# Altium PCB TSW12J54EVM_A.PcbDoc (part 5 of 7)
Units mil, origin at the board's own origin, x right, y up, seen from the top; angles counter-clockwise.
Board outline 6301 x 2680 mil, 10 copper layers (Top Layer - L1, Gnd-Plane - L2, Signals - L3, Gnd-Plane - L4, Pwr Plane - L5, Signals - L6, Gnd-Plane - L7, Signals - L8, Gnd-Plane - L9, Bottom Layer - L10), stack 57.8 mil thick; 650 components, 374 nets, 2074 pads, 1402 vias.
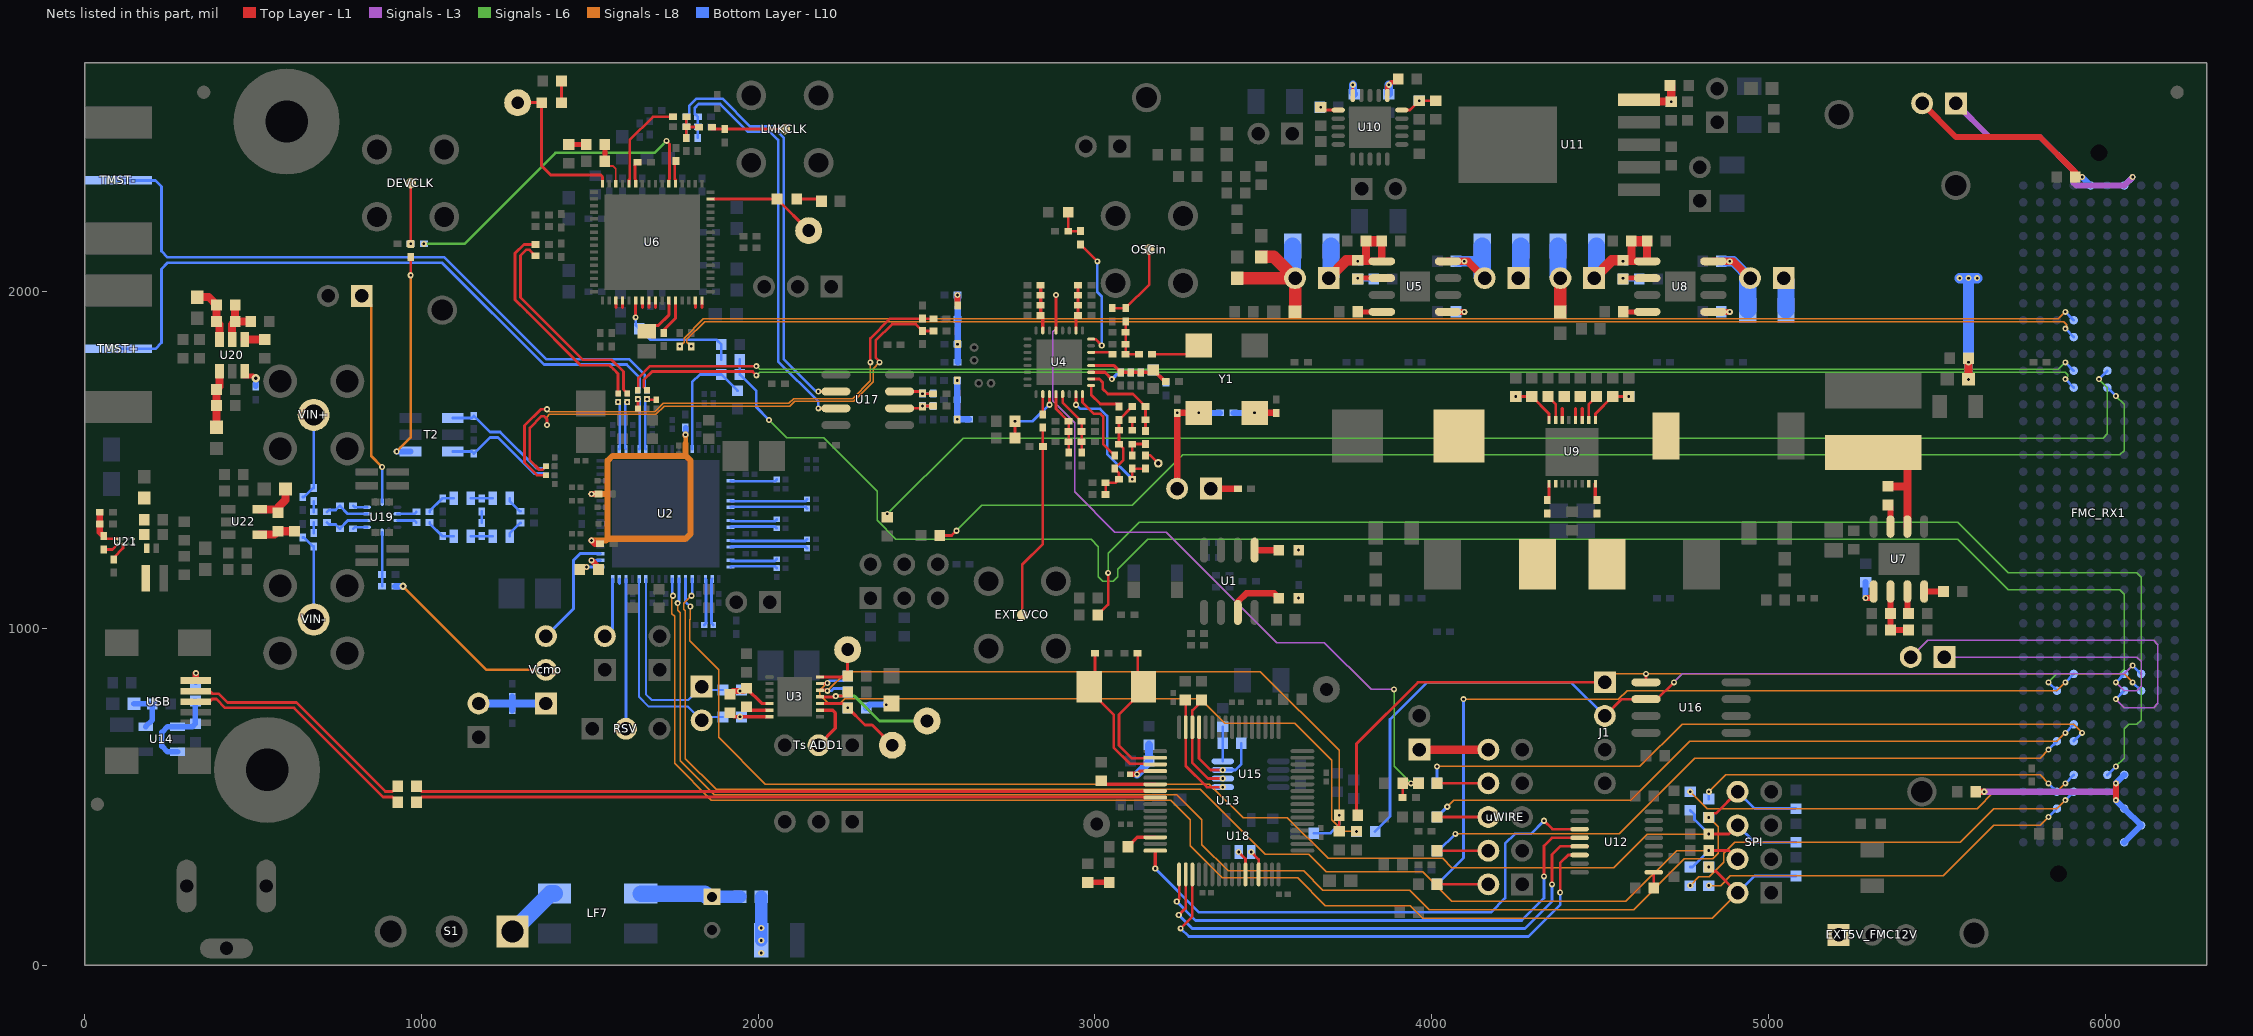
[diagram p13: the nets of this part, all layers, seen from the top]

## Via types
v1: diameter 18, hole 8, Top Layer - L1 to Bottom Layer - L10, tented both sides, 1120 vias
v2: diameter 19.68, hole 7.87, Top Layer - L1 to Bottom Layer - L10, 99 vias
v3: diameter 18, hole 8, Top Layer - L1 to Bottom Layer - L10, tented bottom, 42 vias
v4: diameter 18, hole 8, Top Layer - L1 to Bottom Layer - L10, tented top, 36 vias
v5: diameter 25, hole 10, Top Layer - L1 to Bottom Layer - L10, tented both sides, 32 vias
v6: diameter 21.46, hole 10, Top Layer - L1 to Bottom Layer - L10, tented both sides, 26 vias
v7: diameter 18, hole 8.01, Top Layer - L1 to Bottom Layer - L10, tented both sides, 16 vias
v8: diameter 18, hole 8.01, Top Layer - L1 to Bottom Layer - L10, tented bottom, 16 vias
v9: diameter 25.98, hole 12.99, Top Layer - L1 to Bottom Layer - L10, tented top, 8 vias
v10: diameter 19.68, hole 7.87, Top Layer - L1 to Bottom Layer - L10, tented top, 5 vias
v11: diameter 126, hole 106, Top Layer - L1 to Bottom Layer - L10, tented top, 2 vias

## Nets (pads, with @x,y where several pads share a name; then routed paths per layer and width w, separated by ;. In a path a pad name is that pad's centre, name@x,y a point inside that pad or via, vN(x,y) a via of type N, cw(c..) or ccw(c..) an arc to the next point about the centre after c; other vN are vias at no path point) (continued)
NetC14_2: C14.2 U2.38 | length 139.9
  Bottom Layer - L10 w8: U2.38@1918.3,1438.43 1920.14,1436.58 2049.7,1436.58 C14.2@2055.2,1442.08
NetC15_2: C15.2 U2.42 | length 229.9
  Bottom Layer - L10 w8: U2.42@1918.3,1359.68 1920.14,1361.53 2139.7,1361.53 C15.2@2145.2,1356.03
NetC16_2: C16.2 C18.2 C19.2 U2.5 U2.12 U2.29 | length 1287.4
  Top Layer - L1 w18: v1(1505.26,1261.26) 1515.31,1251.21 C18.2@1530.57,1251.2 ; v1(1505.26,1399.05) C19.2@1525.52,1399.05
  Signals - L8 w13: 1784.44,1549.33 v1@1784.44,1570.92
  Signals - L8 w18: v1(1505.26,1261.26) 1548.22,1261.26 1553.14,1266.18 ; v1(1505.26,1399.05) 1553.14,1399.05 ; 1552.79,1497.48 1567.56,1512.24 1784.79,1512.24 ; 1553.14,1497.83 1553.14,1266.18 ; 1784.44,1549.33 1784.44,1512.59 1799.2,1497.83 1799.2,1280.6 1784.79,1266.18 1553.14,1266.18 ; v1@1784.44,1570.92 v1(1784.44,1575.13)
  Bottom Layer - L10 w9: v1(1505.26,1261.26) U2.5@1532.47,1261.26 ; v1(1505.26,1399.05) U2.12@1532.47,1399.06 ; U2.29@1784.44,1532.91 v1(1784.44,1575.13)
  Bottom Layer - L10 w16: v1(1784.44,1575.13) C16.2@1784.44,1595.94
NetC17_2: C17.2 U2.41 | length 229.9
  Bottom Layer - L10 w8: U2.41@1918.3,1379.37 1920.14,1377.53 2139.7,1377.53 C17.2@2145.2,1383.03
NetC20_2: C20.2 U2.45 | length 139.9
  Bottom Layer - L10 w8: U2.45@1918.3,1300.63 1920.14,1302.47 2049.7,1302.47 C20.2@2055.2,1296.97
NetC21_2: C21.2 U2.44 | length 139.9
  Bottom Layer - L10 w8: U2.44@1918.3,1320.31 1920.14,1318.47 2049.7,1318.47 C21.2@2055.2,1323.97
NetC22_2: C22.2 R7.2 U2.48 | length 229.9
  Bottom Layer - L10 w8: U2.48@1918.3,1241.57 1920.14,1243.42 2139.7,1243.42 R7.2@2145.2,1237.92
NetC23_2: C23.2 U2.47 | length 229.9
  Bottom Layer - L10 w8: U2.47@1918.3,1261.26 1920.14,1259.42 2139.7,1259.42 C23.2@2145.2,1264.92
NetC26_2: C26.2 R8.2 U2.51 | length 139.9
  Bottom Layer - L10 w8: U2.51@1918.3,1182.52 1920.14,1184.36 2049.7,1184.36 R8.2@2055.2,1178.86
NetC28_2: C28.2 U2.50 | length 139.9
  Bottom Layer - L10 w8: U2.50@1918.3,1202.2 1920.14,1200.36 2049.7,1200.36 C28.2@2055.2,1205.86
NetC29_2: C29.2 R9.2 U2.54 | length 139.9
  Bottom Layer - L10 w8: R9.2@1839.84,1010.18 1845.34,1015.68 1845.34,1145.24 U2.54@1843.5,1147.09
NetC30_2: C30.2 C229.1 T2.4 | length 345.5
  Bottom Layer - L10 w8: T2.4@1093.25,1524.95 1149.67,1524.95 C229.1@1155.85,1518.77 1204.03,1566.95 1227.41,1566.95 1334.41,1459.95 1364.09,1459.95 C30.2@1369.59,1454.45
NetC31_2: C31.2 U2.53 | length 139.9
  Bottom Layer - L10 w8: U2.53@1863.18,1147.09 1861.34,1145.24 1861.34,1015.69 C31.2@1866.84,1010.19
NetC34_1: C34.1 U3.6 | length 72.4
  Top Layer - L1 w10: C34.1@1965.28,767.44 1975.33,757.39 U3.6@2033.47,757.39
NetC34_2: C34.2 C38.2 R100.2 U3.5 | length 143.5
  Top Layer - L1 w10: C34.2@1965.28,822.56 2010.76,777.07 U3.5@2033.47,777.07
  Top Layer - L1 w18: C38.2@1916.28,804.56 1925.72,814 1956.72,814 C34.2@1965.28,822.56
  other v1: 1945.78,814
NetC36_2: C36.2 C228.1 T2.6 | length 345.5
  Bottom Layer - L10 w8: T2.6@1093.25,1624.95 1149.67,1624.95 C228.1@1155.85,1631.14 1204.03,1582.95 1234.03,1582.95 1341.03,1475.95 1364.09,1475.95 C36.2@1369.59,1481.45
NetC38_1: C38.1 R99.2 U3.7 | length 122.1
  Top Layer - L1 w10: C38.1@1916.28,749.44 1928.02,737.7 U3.7@2033.47,737.7
  other v1: 1945.78,737.7
NetC73_2: C73.2 C74.2 J2.2 R133.2 Y1.4 | length 352.6
  Top Layer - L1 w19.68: J2.2@3244,1415 v1(3244,1640) v1(3308.56,1640)
  Bottom Layer - L10 w18: v1(3308.56,1640) R133.2@3371.55,1640
NetC76_2: C76.2 R33.2 R162.2 R163.1 U17.2 | length 134.6
  Top Layer - L1 w8: U17.2@2419.82,1653.5 2481.36,1653.5 v1(2488.05,1660.18) C76.2@2519.36,1660.18 C76.2@2520.36,1660.18
  Bottom Layer - L10 w8: v1(2488.05,1660.18) R163.1@2519.36,1660.18
NetC77_1: C77.1 C78.1 C81.1 L1.2 R27.1 R34.1 | length 230.8
  Top Layer - L1 w18: R27.1@2592.05,1959.18 v1(2592.05,1990)
  Bottom Layer - L10 w19.68: L1.2@2592.05,1790 v1(2592.05,1843.81) v1(2592.05,1990)
NetC79_1: C79.1 C80.1 C82.1 L34.2 R28.1 R35.1 | length 149.6
  Bottom Layer - L10 w19.68: v1(2591.05,1736.18) v1(2591.05,1620.81) L34.2@2625.32,1620.82
NetC84_2: C84.2 R37.2 R162.1 R164.1 U17.3 | length 126.1
  Top Layer - L1 w8: U17.3@2419.82,1703.5 R162.1@2481.36,1703.5 ; R162.1@2487.36,1697.5 v1(2488.05,1696.81) C84.2@2519.36,1696.81 C84.2@2520.36,1696.81
  Bottom Layer - L10 w8: v1(2488.05,1696.81) R164.1@2519.36,1696.82
NetC85_2: C85.2 U6.43 | length 67.8
  Top Layer - L1 w8: U6.43@1636.35,2320.23 1636.35,2332.23 1634.5,2334.07 1634.5,2376.19 C85.2@1642.31,2384
NetC86_1: C86.1 C123.2 R48.1 R50.1 | length 99.6
  Top Layer - L1 w8: C123.2@1786.67,2456.69 R50.1@1786.67,2489 ; C86.1@1786.67,2519 R50.1@1786.67,2489 ; R48.1@1823.99,2489 R50.1@1786.67,2489
NetC86_2: C86.2 U6.44 | length 287.6
  Top Layer - L1 w8: U6.44@1616.66,2320.23 1616.66,2332.23 1618.5,2334.07 1618.5,2449.5 1688,2519 C86.2@1747.3,2519
NetC87_1: C87.1 U6.38 | length 978.6
  Top Layer - L1 w8: v1(1727.61,2447.5) 1736.61,2438.5 1736.61,2334.07 1734.77,2332.23 U6.38@1734.77,2320.23
  Signals - L6 w8: v1(1007.43,2141.68) 1127.68,2141.68 1398,2412 1692.12,2412 v1(1727.61,2447.5)
NetC87_2: C87.2 C89.1 DEVCLK.1 R165.2 | length 180.3
  Top Layer - L1 w8: v1(968.06,2141.68) DEVCLK.1@968.06,2322
NetC88_1: C88.1 U6.37 | length 69.3
  Top Layer - L1 w8: U6.37@1754.46,2320.23 1754.46,2332.23 1752.61,2334.07 1752.61,2383.93 C88.1@1756,2387.32
NetC89_2: C89.2 T2.3 | length 636
  Top Layer - L1 w8: v1(968.06,2048.5) C89.2@968.06,2102.31
  Signals - L8 w8: v1(926.57,1524.95) 968.06,1566.43 v1(968.06,2048.5)
  Bottom Layer - L10 w18: v1(926.57,1524.95) T2.3@968.06,1524.95
NetC117_1: C117.1 C126.1 C166.1 LMK_LDO.1 R40.1 R41.2 U5.5 | length 443.2
  Top Layer - L1 w23.5: C117.1@3780,2092.56 3782.56,2090 U5.5@3851.57,2090 C126.1@3851.57,2150 ; 3804.56,2090 C166.1@3804.56,2150
  Top Layer - L1 w31.5: LMK_LDO.1@3694,2040 3746.56,2092.56 C117.1@3777.44,2092.56 ; C166.1@3804.56,2150 C126.1@3851.57,2150
  Bottom Layer - L10 w51: LMK_LDO.1@3694,2040 3701.09,2047.09 R40.1@3701.09,2135.44
  other v1: 3780,2090
NetC117_2: C117.2 R41.1 R49.2 U5.6 | length 120.1
  Top Layer - L1 w15: C117.2@3780,2037.44 3782.56,2040 U5.6@3851.57,2040
  Bottom Layer - L10 w15: R41.1@3780,2037.44 R49.2@3827.44,2037.44
  other v1: 3780,2040
NetC122_1: C122.1 U6.11 | length 129.3
  Top Layer - L1 w9: C122.1@1668.9,1882.27 1686.37,1899.74 1704.3,1899.74 1734.77,1930.21 U6.11@1734.77,1973.77
NetC124_1: C124.1 U6.12 | length 110.9
  Top Layer - L1 w9: C124.1@1719.3,1877.43 1719.3,1885.74 1754.46,1920.9 U6.12@1754.46,1973.77
NetC127_1: C127.1 LMK_INT.2 R42.2 U5.4 | length 304.5
  Top Layer - L1 w23.5: U5.4@4048.43,2090 v1(4096.79,2090) 4107,2090 LMK_INT.2@4157,2040
  Bottom Layer - L10 w31.5: C127.1@4072.05,2090 v1(4096.79,2090) 4149.91,2090
  Bottom Layer - L10 w51: R42.2@4149.91,2134.44 4149.91,2047.09 LMK_INT.2@4157,2040
NetC128_1: C128.1 U5.1 | length 73.1
  Top Layer - L1 w18: U5.1@4048.43,1940 v1(4096.8,1940)
  Bottom Layer - L10 w18: C128.1@4072.05,1940 v1(4096.8,1940)
NetC135_1: C135.1 U13.2 Y2.1 | length 435
  Top Layer - L1 w8: C135.1@3126.65,926 3126.65,844.53 Y2.1@3144.18,827 3144.18,816.71 3071.47,744 3071.47,652.63 3109.99,614.11 3144.63,614.11 3146.47,615.95 U13.2@3178.97,615.95
NetC137_1: C137.1 U13.3 Y2.2 | length 461.5
  Top Layer - L1 w8: C137.1@3000.29,926 3000.29,844.53 Y2.2@2982.76,827 2982.76,816.71 3055.47,744 3055.47,646 3103.36,598.11 3144.63,598.11 3146.47,596.27 U13.3@3178.97,596.27
NetC141_1: C141.1 C142.1 L25.2 U13.4 | length 182.2
  Top Layer - L1 w10: v1(3124.5,566.74) 3134.34,576.58 U13.4@3178.97,576.58
  Top Layer - L1 w16.5: C142.1@3103.44,566.74 v1(3124.5,566.74)
  Bottom Layer - L10 w24: v1(3124.5,566.74) 3160.56,602.8 C141.1@3160.56,606 L25.2@3160.56,654.44
NetC148_1: C148.1 L8.1 U7.6 | length 378.7
  Top Layer - L1 w23.62: L8.1@5311,1522.46 5412,1522.46 U7.6@5412,1302.46 ; C148.1@5354.27,1421.56 5412,1421.56
NetC148_2: C148.2 U7.7 | length 67.2
  Top Layer - L1 w18: C148.2@5354.27,1366.44 5362,1358.71 U7.7@5362,1302.46
NetC149_1: C149.1 C150.1 C151.1 LMX_LDO.1 R73.1 R74.2 U8.5 | length 442.2
  Top Layer - L1 w23.5: C149.1@4568,2092.56 4570.56,2090 U8.5@4639.57,2090 C151.1@4639.57,2150 ; 4592.56,2090 C150.1@4592.56,2150
  Top Layer - L1 w31.5: LMX_LDO.1@4482,2040 4534.56,2092.56 C149.1@4565.44,2092.56 ; C150.1@4592.56,2150 C151.1@4639.57,2150
  Bottom Layer - L10 w51: LMX_LDO.1@4482,2040 4489.09,2047.09 R73.1@4489.09,2134.44
  other v1: 4568,2090
NetC149_2: C149.2 R74.1 R77.2 U8.6 | length 120.1
  Top Layer - L1 w15: C149.2@4568,2037.44 4570.56,2040 U8.6@4639.57,2040
  Bottom Layer - L10 w15: R74.1@4568,2037.44 R77.2@4615.44,2037.44
  other v1: 4568,2040
NetC154_1: C154.1 R72.2 R76.2 U7.2 | length 168
  Top Layer - L1 w18: U7.2@5362,1109.54 R72.2@5362,995 R76.2@5415.44,995
NetC155_1: C155.1 U7.3 | length 65.5
  Top Layer - L1 w18: C155.1@5412,1044 U7.3@5412,1109.54
NetC158_1: C158.1 C159.1 L7.2 LMK_INT.1 LMX_INT.1 R42.1 R75.1 | length 610.3
  Top Layer - L1 w24: v1(5593.5,1739.21) C159.1@5593.5,1802
  Bottom Layer - L10 w24: v1(5593.5,1739.21) C158.1@5593.5,1802
  Bottom Layer - L10 w31.5: v1(5567.5,2040) v1(5619.5,2040) ; C158.1@5593.5,1802 v1(5593.5,2040)
  Bottom Layer - L10 w51: LMK_INT.1@4257,2040 4264.09,2047.09 R42.1@4264.09,2134.44 ; LMX_INT.1@5045,2040 5052.09,2032.91 R75.1@5052.09,1945.56
  other v1: 5593.5,1790
NetC160_1: C160.1 LMX_INT.2 R75.2 U8.4 | length 332.3
  Top Layer - L1 w23.5: U8.4@4836.43,2090 v1(4884.79,2090) 4895,2090 LMX_INT.2@4945,2040
  Bottom Layer - L10 w31.5: C160.1@4860.05,2090 v1(4884.79,2090) 4895,2090 LMX_INT.2@4945,2040
  Bottom Layer - L10 w51: R75.2@4937.91,1945.56 4937.91,2032.91 LMX_INT.2@4945,2040
NetC161_1: C161.1 U8.1 | length 73.1
  Top Layer - L1 w18: U8.1@4836.43,1940 v1(4884.8,1940)
  Bottom Layer - L10 w18: C161.1@4860.05,1940 v1(4884.8,1940)
NetC162_1: C162.1 U7.4 | length 57.4
  Top Layer - L1 w18: U7.4@5462,1109.54 C162.1@5519.44,1109.54
NetC168_1: C168.1 R78.2 U9.3 U9.4 U9.6 | length 100.5
  Top Layer - L1 w10: U9.6@4387.47,1618.49 4387.47,1652 ; U9.4@4426.84,1618.49 4426.84,1652 ; U9.3@4446.53,1618.49 4446.53,1652
NetC169_1: C169.1 U9.16 | length 50.8
  Top Layer - L1 w10: U9.16@4485.9,1429.51 4485.9,1385.53 C169.1@4490.74,1380.68
NetC169_2: C169.2 D11.1 L11.2 U9.15
NetC170_1: C170.1 D12.1 L12.1 U9.10
NetC170_2: C170.2 U9.9 | length 50.8
  Top Layer - L1 w10: C170.2@4343.26,1380.69 4348.1,1385.53 U9.9@4348.1,1429.51
NetC174_1: C174.1 R81.2 R86.2 U9.1 | length 139.1
  Top Layer - L1 w8: U9.1@4485.9,1618.49 4485.9,1637.34 R86.2@4537,1688.44 v1(4585,1688.44)
NetC175_2: C175.2 R82.1 R87.2 U9.8 | length 139.1
  Top Layer - L1 w8: v1(4249,1688.44) R87.2@4297,1688.44 4348.1,1637.34 U9.8@4348.1,1618.49
NetC178_1: C178.1 U9.2 | length 79.4
  Top Layer - L1 w8: U9.2@4466.21,1618.49 4466.21,1665.65 C178.1@4489,1688.44
NetC179_1: C179.1 U9.7 | length 79.4
  Top Layer - L1 w8: C179.1@4345,1688.44 4367.79,1665.65 U9.7@4367.79,1618.49
NetC186_1: C186.1 R79.1 R90.2 U10.10 | length 111.9
  Top Layer - L1 w8: U10.10@3911.16,2539.18 3935.3,2539.18 v1(3962.68,2566.56) R79.1@4011.68,2566.56
NetC187_1: C187.1 U10.15 | length 61.2
  Top Layer - L1 w8: U10.15@3765.49,2582.49 v1(3765.49,2614.17)
  Bottom Layer - L10 w24: v1(3765.49,2614.17) 3765.49,2590.61 C187.1@3769.67,2586.43
NetC192_2: C192.2 R93.1 R96.2 U11.5 | length 147.7
  Top Layer - L1 w24: U11.5@4615.22,2569.86 4621.13,2563.95 v1(4711,2563.95) 4711,2608.44 R96.2@4707.44,2612
NetC193_1: C193.1 L17.1 LF7.3 | length 298.8
  Bottom Layer - L10 w37: C193.1@1851,202.76 L17.1@1946.16,202.76
  Bottom Layer - L10 w49: LF7.3@1651.46,212.6 1841.16,212.6 C193.1@1851,202.76
NetC194_1: C194.1 EXT5V_FMC12V.1 L17.2 | length 129.3
  Bottom Layer - L10 w37: C194.1@2009.15,73.49 L17.2@2009.15,202.76
  other v1: 2009.15,36.28 2009.15,73.49 2009.15,110.7
NetC201_1: C201.1 R103.2 U14.1 U14.3 | length 271.6
  Bottom Layer - L10 w16.5: U14.3@275.94,633.46 246.64,633.46 229.76,650.33 229.76,691.39 246.64,708.26 U14.1@275.94,708.26 320.38,708.26 C201.1@329.24,717.12 R103.2@329.24,784.4
NetC211_1: C211.1 L26.1 U14.5 | length 130.2
  Bottom Layer - L10 w16.5: L26.1@146.73,775.86 C211.1@201.14,775.86 201.14,727.95 U14.5@181.46,708.26
NetC230_1: C230.1 C231.2 C232.1 C233.1 L27.2 U4.27 | length 256.3
  Top Layer - L1 w9.45: U4.27@2988.72,1760.47 3029.69,1760.47 v1(3050.17,1740)
  Bottom Layer - L10 w11.02: v1(3050.17,1740) 3070.64,1760.47 C233.1@3076.33,1760.47 C232.1@3106.33,1760.47 C231.2@3136.33,1760.47 3166.46,1760.47 C230.1@3173.33,1767.35 L27.2@3210,1730.68
NetC234_1: C234.1 C235.2 C236.1 C237.1 L28.2 U4.28 | length 244
  Top Layer - L1 w9.45: U4.28@2988.72,1780.16 3056.65,1780.16 C237.1@3076.33,1760.47
  Top Layer - L1 w11.02: C237.1@3076.33,1760.47 C236.1@3106.33,1760.47 C235.2@3136.33,1760.47 3166.46,1760.47 C234.1@3173.33,1767.35 L28.2@3207.55,1733.13
NetC238_1: C238.1 C239.1 C240.1 L29.2 U4.21 | length 196.5
  Top Layer - L1 w8: U4.21@2904.08,1695.51 2904.08,1671.16 C238.1@2960.55,1614.68 C239.1@2960.55,1584.68 C240.1@2960.55,1554.68 L29.2@2960.55,1522.37
NetC241_1: C241.1 C242.1 C243.1 L30.2 U4.20 | length 188.7
  Top Layer - L1 w8: U4.20@2884.39,1695.51 2884.39,1652.21 C241.1@2921.92,1614.68 C242.1@2921.92,1584.68 C243.1@2921.92,1554.68 L30.2@2921.92,1522.37
NetC244_1: C244.1 C245.1 R91.1 U4.26 | length 278.6
  Top Layer - L1 w8: U4.26@2988.72,1740.79 3013.08,1740.79 3023.14,1730.72 3023.14,1711.28 3038.33,1696.09 3112.57,1696.09 C245.1@3149.98,1658.68 C244.1@3149.98,1619.31 R91.1@3149.98,1586.68
NetC244_2: C244.2 R144.2 | length 31.3
  Top Layer - L1 w8: R144.2@3110.61,1588 C244.2@3110.61,1619.31
NetC245_2: C245.2 C246.2 C247.2 R144.1 R145.2 R146.2 R147.1 R149.1 | length 332.4
  Top Layer - L1 w8: R147.1@3031.68,1397.5 R146.2@3031.68,1432.5 3060.74,1432.5 C247.2@3071.24,1443 3071.24,1461.31 R149.1@3058.24,1474.31 3084.24,1500.31 3084.24,1534.31 C246.2@3071.24,1547.31 R144.1@3071.24,1588 R145.2@3071.24,1619.31 C245.2@3110.61,1658.68
NetC246_1: C246.1 R91.2 R148.1 | length 73
  Top Layer - L1 w8: R148.1@3110.61,1513.68 C246.1@3110.61,1547.31 R91.2@3149.98,1547.31
NetC247_1: C247.1 R148.2 R150.1 U4.23 | length 426.8
  Top Layer - L1 w8: v1@2943.45,1664.93 U4.23@2943.45,1695.51 ; v1(3110.61,1443) R148.2@3110.61,1474.31 R150.1@3149.98,1474.31
  Bottom Layer - L10 w8: v1@2943.45,1664.93 2956.38,1652 3015,1652 3036,1631 3036,1517.61 v1(3110.61,1443)
  other v1: 2943.45,1664.07
NetC248_1: C248.1 U4.18 | length 59.8
  Top Layer - L1 w8: C248.1@2845.02,1635.68 U4.18@2845.02,1695.51
NetC248_2: C248.2 EXT_VCO.1 R153.2 | length 581.6
  Top Layer - L1 w8: EXT_VCO.1@2784.02,1040 2784.02,1190.02 2845.02,1251.02 R153.2@2845.02,1540 C248.2@2845.02,1596.31
NetC249_1: C249.1 U4.30 | length 65.3
  Top Layer - L1 w8: U4.30@2988.72,1819.53 3045.8,1819.53 C249.1@3051.65,1813.69
NetC249_2: C249.2 C251.2 R24.2 R25.2 R38.1 | length 137
  Top Layer - L1 w8: R25.2@3091.02,1911.41 C249.2@3091.02,1813.69 R38.1@3130.32,1813.68
NetC250_2: C250.2 LD.1 R154.1 | length 92.3
  Top Layer - L1 w8: LD.1@2920.69,2235.37 C250.2@2920.68,2179.37 R154.1@2957,2179.37
NetC252_1: C252.1 C253.1 C254.1 L32.2 U4.2 | length 137.2
  Top Layer - L1 w8: C254.1@2949.75,1929.09 L32.2@2949.75,2019.09
  Top Layer - L1 w9.45: U4.2@2943.45,1884.49 2943.45,1922.8 C254.1@2949.75,1929.09
NetC255_1: C255.1 C256.1 C257.1 L33.2 U4.7 | length 137.2
  Top Layer - L1 w9.45: C257.1@2838.72,1929.09 2845.02,1922.8 U4.7@2845.02,1884.49
  Top Layer - L1 w11.02: C257.1@2838.72,1929.09 C256.1@2838.72,1959.09 C255.1@2838.72,1989.09 L33.2@2838.72,2019.09
NetC272_2: C272.2 R178.2 U19.2 | length 159.9
  Bottom Layer - L10 w8: R178.2@883.61,1125 C272.2@883.61,1160 U19.2@883.61,1284.88
NetC276_1: C276.1 C277.1 L35.2 U20.1 | length 169.9
  Top Layer - L1 w24: L35.2@391.73,1597.02 C276.1@391.73,1661.52 C277.1@391.73,1709.52 400.59,1718.38 U20.1@400.59,1763.28
NetC278_1: C278.1 U20.4 | length 59.6
  Top Layer - L1 w24: U20.4@475.4,1857.77 C278.1@534.99,1857.77
NetC279_1: C279.1 L43.1 R171.1 U20.6 | length 172.7
  Top Layer - L1 w24: L43.1@335,1983.5 368.76,1983.5 C279.1@391.73,1960.52 R171.1@391.73,1911.52 400.59,1902.66 U20.6@400.59,1857.77
NetC279_2: C279.2 R171.2 R172.2 U20.5 | length 153
  Top Layer - L1 w24: U20.5@437.99,1857.77 437.99,1902.67 R171.2@446.85,1911.52 ; C279.2@446.85,1960.52 R171.2@446.85,1911.52 ; R172.2@493.43,1911.52 R171.2@446.85,1911.52
NetC282_1: C282.1 C283.1 L36.2 U21.D2
NetC286_2: C286.2 R174.1 R175.2 U21.A2 | length 125.3
  Top Layer - L1 w8: R175.2@56.73,1273.67 56.73,1265.86 U21.A2@98.11,1265.86
  Top Layer - L1 w19: C286.2@45.05,1344.99 R174.1@45.05,1309.99 45.05,1285.36 R175.2@56.73,1273.67
NetC291_1: C291.1 L38.1 Ro+.2 | length 90.3
  Bottom Layer - L10 w8: Ro+.2@1024.47,1314.47 1024.47,1311.47 1061.96,1273.97 L38.1@1096.24,1273.97
NetC292_2: C292.2 L39.1 Ro-.2 | length 90.3
  Bottom Layer - L10 w8: Ro-.2@1024.47,1345.84 1024.47,1348.85 1061.96,1386.34 L39.1@1096.24,1386.34
NetC293_1: C293.1 L38.2 L40.1 | length 64.9
  Bottom Layer - L10 w8: L38.2@1146.64,1273.97 C293.1@1179.1,1273.97 L40.1@1211.55,1273.97
NetC293_2: C293.2 C294.1 | length 33.6
  Bottom Layer - L10 w8: C293.2@1179.1,1313.34 C294.1@1179.1,1346.97
NetC294_2: C294.2 L39.2 L41.1 | length 64.9
  Bottom Layer - L10 w8: L39.2@1146.64,1386.34 L41.1@1211.55,1386.34
NetC295_1: C295.1 Ri-.1 | length 31.8
  Bottom Layer - L10 w8: C295.1@680.41,1282.68 Ri-.1@680.41,1314.47
NetC295_2: C295.2 R168.2 VIN-.1 | length 260.2
  Bottom Layer - L10 w8: R168.2@648,1269.98 651.34,1269.98 678,1243.31 C295.2@680.41,1243.31 VIN-.1@680.41,1026.53
NetC296_1: C296.1 R169.2 | length 31.8
  Bottom Layer - L10 w8: R169.2@680.41,1345.84 C296.1@680.41,1377.63
NetC296_2: C296.2 Ri+.2 VIN+.1 | length 260.2
  Bottom Layer - L10 w8: Ri+.2@648,1390.34 651.34,1390.34 678,1417 C296.2@680.41,1417 VIN+.1@680.41,1633.79
NetD1_1: D1.1 L37.1 U21.D1
NetEXT_Vcmo_2: EXT_Vcmo.2 R182.2 R183.2 Vcmo.1 | length 238.6
  Bottom Layer - L10 w19.68: R183.2@1269.78,757.69 1269.78,777 R182.2@1269.78,796.31
  Bottom Layer - L10 w25: EXT_Vcmo.2@1169.78,777 Vcmo.1@1369.78,777
NetFMC_RX1_C30: FMC_RX1.C30 J1.2 R127.2 U16.6 | length 2740.7
  Top Layer - L1 w8: J1.2@4514,740 4564,790 U16.6@4636.14,790 4669.2,790 v1(4719.2,840)
  Signals - L3 w4: v1(4719.2,840) 4744.2,865 6056,865 v3(6081,890)
  Bottom Layer - L10 w8: R127.2@3831.68,397.13 3876,441.45 3876,730 3986,840 4414,840 J1.2@4514,740 ; v3(6081,890) FMC_RX1.C30@6106,865
NetFMC_RX1_C31: FMC_RX1.C31 J1.1 R126.2 U16.5 | length 2673.6
  Top Layer - L1 w8: R126.2@3776.56,445 3776.56,657.56 3959,840 J1.1@4514,840 ; U16.5@4636.14,840 v1(4636.14,865)
  Signals - L8 w4: J1.1@4514,840 4539,865 6056,865 v3(6081,840)
  Bottom Layer - L10 w8: v3(6081,840) FMC_RX1.C31@6106,815
NetFMC_RX1_C39: FMC_RX1.C39 FMC_RX1.D36 FMC_RX1.D38 FMC_RX1.D40 R132.2 | length 727.6
  Top Layer - L1 w18: R132.2@5615.56,515 v1(5640.31,515) ; v1(6031,490) v1(6031,540)
  Signals - L3 w18: v1(5640.31,515) 6031,515 ; v1(6031,490) v1(6031,540)
  Bottom Layer - L10 w18: v1(6031,490) FMC_RX1.D38@6056,465 FMC_RX1.C39@6106,415 FMC_RX1.D40@6056,365 ; v1(6031,540) FMC_RX1.D36@6056,565
NetFMC_RX1_D30: "KC705 JTAG.1" FMC_RX1.D30 | length 789.5
  Signals - L3 w4: 5522,915 6093,915 6106,902 6106,828 6093,815 6056,815 v3(6031,840)
  Bottom Layer - L10 w8: v3(6031,840) FMC_RX1.D30@6056,865
NetFMC_RX1_D31: "KC705 JTAG.2" FMC_RX1.D31 | length 1110.2
  Signals - L3 w4: 5422,915 5472,965 6143,965 6156,952 6156,778 6143,765 6056,765 v3(6031,790)
  Bottom Layer - L10 w8: v3(6031,790) FMC_RX1.D31@6056,815
NetFMC_RX1_E12: FMC_RX1.E12 R136.2 | length 3928.8
  Signals - L6 w4: v1(2383.5,1340) 2608.5,1565 5993,1565 6006,1578 6006,1715 v3(5981,1740)
  Bottom Layer - L10 w8: v3(5981,1740) FMC_RX1.E12@6006,1765
NetFMC_RX1_E13: FMC_RX1.E13 R137.2 | length 3829.5
  Top Layer - L1 w8: R137.2@2538.62,1276 2574.62,1276 v1(2588.62,1290)
  Signals - L6 w4: v1(2588.62,1290) 2663.62,1365 3111,1365 3261,1515 6043,1515 6056,1528 6056,1665 v3(6031,1690)
  Bottom Layer - L10 w8: FMC_RX1.E13@6006,1715 v3(6031,1690)
NetFMC_RX1_E36: FMC_RX1.E36 R138.2 | length 4010.9
  Top Layer - L1 w8: R138.2@3008.06,1040 3039,1070.94 v1(3039,1165)
  Signals - L6 w4: v1(3039,1165) 3039,1223 3131,1315 5561,1315 5711,1165 6093,1165 6106,1152 6106,728 6093,715 6069,715 6056,702 6056,615 v3(6031,590)
  Bottom Layer - L10 w8: FMC_RX1.E36@6006,565 v3(6031,590)
NetFMC_RX1_G30: FMC_RX1.G30 R121.2 | length 2425
  Signals - L8 w4: v1@4094.99,789.01 4554.01,789.01 4580,815 5856,815 v3(5881,840)
  Bottom Layer - L10 w8: R121.2@4015.56,240 4094,318.44 v1(4094,790) ; v3(5881,840) FMC_RX1.G30@5906,865
NetFMC_RX1_G33: FMC_RX1.G33 R69.2 | length 2004.3
  Signals - L8 w4: v1(4046,470.44) 4065.56,490 4591,490 4766,665 5856,665 v3(5881,690)
  Bottom Layer - L10 w8: R69.2@4015.56,440 v1(4046,470.44) ; v3(5881,690) FMC_RX1.G33@5906,715
NetFMC_RX1_G34: FMC_RX1.G34 R119.2 | length 2062.9
  Signals - L8 w4: v1(4015.56,590) 4618,590 4743,715 5906,715 v3(5931,690)
  Bottom Layer - L10 w8: R119.2@4015.56,540 v1(4015.56,590) ; FMC_RX1.G34@5906,665 v3(5931,690)
NetFMC_RX1_G36: FMC_RX1.G36 R57.2 | length 1200.7
  Signals - L8 w4: v1(4767.44,515) 4817.44,465 5619,465 5669,515 5856,515 v3(5881,540)
  Bottom Layer - L10 w8: v3(5881,540) FMC_RX1.G36@5906,565
NetFMC_RX1_G37: FMC_RX1.G37 R55.2 | length 1269.8
  Signals - L8 w4: v1(4767.44,236.38) 4793.06,262 4824,262 4867,305 4867,332 4900,365 5569,365 5669,465 5856,465 v3(5881,490)
  Bottom Layer - L10 w8: v3(5881,490) FMC_RX1.G37@5906,515
NetFMC_RX1_H34: FMC_RX1.H34 R120.2 | length 1975.1
  Signals - L8 w4: v1(4070,390) 4556,390 4781,615 5806,615 v3(5831,640)
  Bottom Layer - L10 w8: R120.2@4015.56,340 4020,340 v1(4070,390) ; v3(5831,640) FMC_RX1.H34@5856,665
NetFMC_RX1_H37: FMC_RX1.H37 R58.2 | length 1096.2
  Signals - L8 w4: v1(4822.56,515) 4872.56,565 5806,565 v3(5831,540)
  Bottom Layer - L10 w8: R58.2@4822.56,493.62 v1(4822.56,515) ; v3(5831,540) FMC_RX1.H37@5856,515
NetFMC_RX1_H38: FMC_RX1.H38 R54.2 | length 1128.1
  Signals - L8 w4: v1(4822.56,236.38) 4857.38,236.38 4886,265 5519,265 5669,415 5806,415 v3(5831,440)
  Bottom Layer - L10 w8: v3(5831,440) FMC_RX1.H38@5856,465
NetJ2_1: J2.1 L31.2 | length 80.3
  Top Layer - L1 w19.68: J2.1@3344,1415 L31.2@3424.31,1415
NetJ3_1: J3.1 uWIRE.10 | length 205
  Top Layer - L1 w25: J3.1@3963,640 uWIRE.10@4168,640
NetL6_1: L6.1 LMX_LDO.2 R73.2 | length 197.9
  Top Layer - L1 w37: L6.1@4382,1939.5 LMX_LDO.2@4382,2040
  Bottom Layer - L10 w51: R73.2@4374.91,2134.44 4374.91,2047.09 LMX_LDO.2@4382,2040
NetL9_1: L9.1 L10.1 L13.1 LMK_LDO.2 R40.2 | length 496.5
  Top Layer - L1 w37: L13.1@3422,2040 LMK_LDO.2@3594,2040 ; L10.1@3494,2103 3531,2103 LMK_LDO.2@3594,2040 ; L9.1@3594,1940 LMK_LDO.2@3594,2040
  Bottom Layer - L10 w51: R40.2@3586.91,2135.44 3586.91,2047.09 LMK_LDO.2@3594,2040
NetL40_2: L40.2 R179.1 | length 53.8
  Bottom Layer - L10 w8: L40.2@1261.95,1273.97 1261.95,1281.95 1292.84,1312.84 R179.1@1294.95,1312.84
NetL41_2: L41.2 R180.1 | length 53.8
  Bottom Layer - L10 w8: L41.2@1261.95,1386.34 1261.95,1378.37 1292.84,1347.47 R180.1@1294.95,1347.47
NetL44_1: L44.1 R176.2 U22.5 | length 137.4
  Top Layer - L1 w24: U22.5@520.56,1353.4 564.47,1353.4 R176.2@574.32,1343.56 574.32,1359.32 596.29,1381.29 L44.1@596.29,1413.99
NetLD1_1: LD1.1 Status1.1 U6.31 | length 330.1
  Top Layer - L1 w9: U6.31@1858.79,2274.95 Status1.1@2055.98,2274.95 LD1.1@2149.93,2181
NetLD2_1: LD2.1 Status2.1 U6.48 | length 473.5
  Top Layer - L1 w9: LD2.1@1286,2561 Status2.1@1356.71,2561 ; Status2.1@1357,2561 1357,2373 1384,2346 1532.65,2346 1537.92,2340.73 U6.48@1537.92,2320.23
NetLF1_1: LF1.1 LF2.1 U6.46 | length 136.1
  Top Layer - L1 w5.5: LF2.1@1544.86,2386.74 1558.86,2372.74 1569.3,2372.74 1577.29,2364.75 U6.46@1577.29,2320.23
  Top Layer - L1 w15: LF2.1@1544.86,2386.74 LF1.1@1544.86,2436.74
NetLF1_2: LF1.2 LF3.2 | length 51.9
  Top Layer - L1 w15: LF3.2@1437.86,2436.74 LF1.2@1489.74,2436.74
NetLF7_2: LF7.2 S1.1 | length 171
  Bottom Layer - L10 w50: S1.1@1271.1,100.2 1383.5,212.6 LF7.2@1395.55,212.6
"NetLMH PD_1": "LMH PD.1" U19.9 | length 637.6
  Signals - L8 w8: 823,1987 849.87,1960.13 851.48,1960.13 851.48,1511.13 v1(883.61,1479)
  Bottom Layer - L10 w8: U19.9@883.61,1375.43 v1(883.61,1479)
NetLMKCLK_1: LMKCLK.1 R48.2 R51.2 | length 216.1
  Top Layer - L1 w8: R48.2@1863.36,2482.51 R51.2@1900.67,2482.5 LMKCLK.1@2079.5,2482.51
NetOR_T0_1: OR_T0.1 U1.1 | length 71.5
  Top Layer - L1 w19.5: U1.1@3474,1232.52 OR_T0.1@3545.47,1232.52
NetOR_T0_2: OR_T0.2 R2.1
  other v1: 3604.53,1232.52
NetOR_T1_1: OR_T1.1 U1.7 | length 169.1
  Top Layer - L1 w19.5: U1.7@3424,1047.48 3424,1079 3449,1104 3531.47,1104 OR_T1.1@3545.47,1090
NetOR_T1_2: OR_T1.2 R10.1
  other v1: 3604.53,1090
NetOSCin_1: OSCin.1 R25.1 R30.2 | length 242.7
  Top Layer - L1 w8: R30.2@3051.65,1950.78 R25.1@3091.02,1950.78 3161.24,2021 OSCin.1@3161.24,2125
NetR13_1: R13.1 U2.2 | length 62.9
  Top Layer - L1 w18: v1(1505.26,1202.2) 1525.82,1181.65 R13.1@1525.82,1175
  Bottom Layer - L10 w9: v1(1505.26,1202.2) U2.2@1532.47,1202.2
NetR13_2: R13.2 U2.1 | length 64.9
  Top Layer - L1 w18: R13.2@1470.7,1175 1478.22,1182.52 v1(1490.26,1182.52)
  Bottom Layer - L10 w9: v1(1490.26,1182.52) U2.1@1532.47,1182.52
NetR17_2: R17.2 TEMP.2 | length 63.6
  Bottom Layer - L10 w18: R17.2@2320.84,763.41 2330.84,773.41 v1(2380.28,773.41)
NetR26_2: R26.2 R133.1 Y1.1 | length 127.6
  Top Layer - L1 w19.68: v1(3473.91,1640) R26.2@3538.47,1640
  Bottom Layer - L10 w18: R133.1@3410.92,1640 v1(3473.91,1640)
NetR31_1: R31.1 R117.1 R124.1 R126.1 U3.12 | length 2085
  Top Layer - L1 w8: R124.1@3725,397.13 3725.44,397.57 v1(3725.44,445)
  Top Layer - L1 w9: U3.12@2183.08,816.44 2203.28,816.44 v1(2205.28,814.44)
  Signals - L8 w4: v1(2205.28,814.44) 2262.46,871.62 3491.38,871.62 3725.44,637.56 v1(3725.44,445)
  Bottom Layer - L10 w8: v1(2205.28,814.44) 2216.96,814.44 2223.99,821.47 2255.66,821.47 R31.1@2265.72,811.41 ; R117.1@3649.81,392.13 3699.13,392.13 3725.44,418.44 v1(3725.44,445)
NetR32_1: R32.1 R125.1 R127.1 U3.13 | length 2012.8
  Top Layer - L1 w9: U3.13@2183.08,836.13 2203.28,836.13 v1(2205.28,838.13)
  Signals - L8 w4: v1(2205.28,838.13) 2183.08,815.93 2183.08,802.92 2208,778 2244,778 2257.44,791.44 3312.89,791.44 3385.33,719 3593,719 3703,609 3703,432 3737.87,397.13 v1(3776.56,397.13)
  Bottom Layer - L10 w8: v1(2205.28,838.13) 2212.15,845 2251.91,845 R32.1@2265.72,858.81
NetR38_2: R38.2 Y1.3 | length 149.8
  Top Layer - L1 w8: R38.2@3169.69,1813.68 3282.24,1813.68 Y1.3@3308.56,1840
NetR39_2: R39.2 U5.8 | length 71
  Top Layer - L1 w15: R39.2@3780.56,1940 U5.8@3851.57,1940
NetR45_2: R45.2 Status2.2 | length 63.7
  Top Layer - L1 w9: Status2.2@1416.05,2561.29 R45.2@1416.06,2625
NetR47_1: R47.1 R142.2 R143.2 U6.6 | length 395.4
  Top Layer - L1 w9: v1(1636.35,1923.69) U6.6@1636.35,1973.77
  Bottom Layer - L10 w8: v1(1636.35,1923.69) 1636.35,1901 R47.1@1647.35,1890 1680.35,1857 1876.44,1857 R142.2@1890.44,1843 R143.2@1890.44,1798.5
NetR52_1: R52.1 USB.2 | length 729.7
  Top Layer - L1 w8: USB.2@330.71,813.93 371.71,813.93 379.46,806.18 397.98,806.18 424.17,780 628.63,780 892.94,515.69 914.24,515.69 R52.1@930.24,531.69
NetR52_2: R52.2 U13.7 | length 2201
  Top Layer - L1 w8: R52.2@985.36,531.69 1001.36,515.69 3144.63,515.69 3146.47,517.53 U13.7@3178.97,517.53
NetR53_1: R53.1 USB.3 | length 729.7
  Top Layer - L1 w8: USB.3@330.71,782.44 371.71,782.44 379.46,790.18 391.36,790.18 417.54,764 622,764 886.31,499.69 914.24,499.69 R53.1@930.24,483.69
NetR53_2: R53.2 U13.8 | length 2201
  Top Layer - L1 w8: R53.2@985.36,483.69 1001.36,499.69 3144.63,499.69 3146.47,497.84 U13.8@3178.97,497.84
NetR54_1: R54.1 R118.1 R139.2 SPI.2 U2.59 | length 4287.8
  Top Layer - L1 w8: v1(4822.56,291.5) 4835.06,279 4844,279 SPI.2@4908,215
  Signals - L8 w4: v1(1747.19,1097) 1744,1093.81 1744,1044 1752,1036 1752,599 1861,490 3225,490 3282.75,432.25 3282.75,354.25 3378,259 3602,259 3684,177 3936,177 3973,140 4833,140 SPI.2@4908,215
  Bottom Layer - L10 w8: U2.59@1745.07,1147.09 1745.07,1099.12 v1(1747.19,1097) ; SPI.2@4908,215 4958,265 R139.2@5081.44,265
NetR55_1: R55.1 R110.1 SPI.4 U2.56 | length 3994.1
  Top Layer - L1 w8: v1(4822.56,340.5) 4882.5,340.5 SPI.4@4908,315
  Signals - L8 w4: v1(1802,1097) 1779,1074 1779,1057 1784,1052 1784,613 1875,522 3313,522 3506,329 3635,329 3687,277 3973,277 4060,190 4576.36,190 4726.86,340.5 v1(4822.56,340.5)
  Bottom Layer - L10 w8: v1(1802,1097) 1804.13,1099.12 U2.56@1804.13,1147.09 ; R55.1@4767.44,291.5 4773.56,291.5 v1(4822.56,340.5)
NetR56_2: R56.2 Status1.2 | length 72.9
  Top Layer - L1 w9: Status1.2@2115.03,2274.95 R56.2@2187.94,2274.95
NetR57_1: R57.1 R111.1 R140.2 SPI.6 U2.57 | length 4037.1
  Top Layer - L1 w8: v1(4822.56,389.5) 4882.5,389.5 SPI.6@4908,415
  Signals - L8 w4: v1(1798.44,1065) 1798.44,1026.44 1797,1025 1797,963 1882.28,877.72 1882.28,676.72 2021,538 3340,538 3440,438 3571,438 3692,317 4032,317 4059,290 4541,290 4640.5,389.5 v1(4822.56,389.5)
  Bottom Layer - L10 w8: U2.57@1784.44,1147.09 1784.44,1079 v1(1798.44,1065) ; R57.1@4767.44,459.88 4780,447.32 4780,432.06 v1(4822.56,389.5) ; SPI.6@4908,415 4958,365 R140.2@5081.44,365
NetR58_1: R58.1 R109.1 R141.2 SPI.8 U2.58 | length 4351.5
  Top Layer - L1 w8: v1(4822.56,438.5) 4835.06,451 4844,451 SPI.8@4908,515
  Signals - L8 w4: v1(1760.76,1075) 1760.76,1054.24 1768,1047 1768,607 1869,506 3243,506 3317,432 3317,358 3395,280 3620,280 3677,223 3934,223 3992,165 4599,165 4750,316 4834,316 4850,332 4850,411.06 v1(4822.56,438.5)
  Bottom Layer - L10 w8: v1(1760.76,1075) 1764.76,1079 U2.58@1764.76,1147.09 ; SPI.8@4908,515 4958,465 R141.2@5081.44,465
NetR65_2: R65.2 U12.9 | length 47
  Top Layer - L1 w8: R65.2@4659.24,229 U12.9@4659.24,275.96
NetR66_1: R66.1 U13.14 | length 92.5
  Top Layer - L1 w10: R66.1@3098.03,351.73 3126.03,379.73 U13.14@3178.97,379.73
NetR67_2: R67.2 U13.6 | length 164.9
  Top Layer - L1 w10: R67.2@3018.47,547.96 3029.22,537.21 U13.6@3178.97,537.21
NetR70_2: R70.2 U7.1 | length 71.1
  Top Layer - L1 w18: v1(5288.19,1090) U7.1@5312,1090
  Bottom Layer - L10 w18: v1(5288.19,1090) R70.2@5288.19,1137.29
NetR71_2: R71.2 U8.8 | length 71
  Top Layer - L1 w15: R71.2@4568.56,1940 U8.8@4639.57,1940
NetR80_2: R80.2 R89.2 U10.11 | length 96
  Top Layer - L1 w13.5: U10.11@3867.86,2582.49 3867.86,2609.67 v1(3872.36,2614.17) 3879.18,2621 3890.1,2621 R80.2@3900.1,2631
  Bottom Layer - L10 w24: R89.2@3872.36,2586.43 v1(3872.36,2614.17)
NetR85_1: R85.1 R88.2 U10.16 | length 55
  Top Layer - L1 w8: v1(3670.68,2547.56) 3679.05,2539.18 U10.16@3722.19,2539.18
NetR97_2: R97.2 uWIRE.8 | length 152.4
  Top Layer - L1 w8: R97.2@4015.56,540 uWIRE.8@4168,540
NetR98_2: R98.2 uWIRE.6 | length 152.4
  Top Layer - L1 w8: R98.2@4015.56,440 uWIRE.6@4168,440
NetR99_1: R99.1 Tdiode.2 U2.64 | length 632.6
  Bottom Layer - L10 w6: U2.64@1646.65,1147.09 1646.65,796.36 1675.35,767.66 1791.62,767.66 Tdiode.2@1832.28,727 ; Tdiode.2@1832,727.28 1841.72,737 R99.1@1895.44,737
NetR100_1: R100.1 Tdiode.1 U2.63 | length 599.4
  Bottom Layer - L10 w6: U2.63@1666.33,1147.09 1666.33,804.52 1683.5,787.34 1792.62,787.34 Tdiode.1@1832.28,827 1842.28,817 R100.1@1895.44,817
NetR101_2: R101.2 uWIRE.4 | length 152.4
  Top Layer - L1 w8: R101.2@4015.56,340 uWIRE.4@4168,340
NetR102_2: R102.2 uWIRE.2 | length 152.4
  Top Layer - L1 w8: R102.2@4015.56,240 uWIRE.2@4168,240
NetR103_1: R103.1 USB.1 | length 49.6
  Top Layer - L1 w19.5: USB.1@330.71,845.43 v1(330.71,867.27)
  Bottom Layer - L10 w16.5: R103.1@330.71,839.52 v1(330.71,867.27)
NetR105_1: R105.1 R108.2 U15.4 | length 102.1
  Bottom Layer - L10 w8: U15.4@3379.32,605.39 R108.2@3379.32,659 R105.1@3379.32,707.44
NetR106_1: R106.1 U13.62 U15.2 | length 307.2
  Top Layer - L1 w8: R106.1@3316.2,787.44 3316.2,783.44 3289.2,756.44 U13.62@3289.2,706.5 3289.2,600.8 3335.8,554.2 v1(3379.32,554.2)
NetR107_1: R107.1 U13.63 U15.1 | length 332.3
  Top Layer - L1 w8: R107.1@3268.2,787.44 3269.52,786.13 U13.63@3269.52,706.5 3269.52,591.48 3332.39,528.61 v1(3379.32,528.61)
NetR108_1: R108.1 U13.61 U15.3 | length 301
  Top Layer - L1 w8: U13.61@3308.89,706.5 3308.89,614.11 3343.2,579.8 v1(3379.32,579.8)
  Bottom Layer - L10 w8: v1(3379.32,579.8) 3416.8,579.8 3434.44,597.44 R108.1@3434.44,659
NetR112_2: R112.2 USB_PWR.2 | length 64
  Top Layer - L1 w16.5: R112.2@2978.91,245.68 USB_PWR.2@3042.91,245.68
NetR134_2: R134.2 R135.2 U2.30 | length 362.2
  Bottom Layer - L10 w8: U2.30@1804.13,1532.91 1804.13,1731.13 1827,1754 R134.2@1890.44,1754 R135.2@1938.64,1705.8
NetR145_1: R145.1 U4.25 | length 120.3
  Top Layer - L1 w8: U4.25@2988.72,1721.1 2988.72,1693.7 3015.93,1666.5 R145.1@3070.33,1666.5
NetR149_2: R149.2 U4.24 | length 232.4
  Top Layer - L1 w8: U4.24@2963.13,1695.51 2963.13,1671.16 2997.2,1637.09 3016.33,1637.09 3024.24,1629.19 3024.24,1547.68 R149.2@3058.24,1513.68
NetR150_2: R150.2 Vtune.1 | length 48.1
  Top Layer - L1 w8: R150.2@3149.98,1513.68 3164.55,1513.68 Vtune.1@3188.24,1490
NetR151_2: R151.2 R152.1 U4.19 | length 203.4
  Top Layer - L1 w8: R152.1@2762.56,1565 v1(2762.56,1615) ; v1@2864.71,1664.93 U4.19@2864.71,1695.51
  Bottom Layer - L10 w8: v1(2762.56,1615) 2814.78,1615 v1@2864.71,1664.93
  other v1: 2864.71,1664.07
NetR154_2: R154.2 U4.32 | length 365.4
  Top Layer - L1 w8: R154.2@2957,2140 v1(3007,2090) ; U4.32@2988.72,1858.9 3001.27,1858.9 v1(3020.17,1840)
  Bottom Layer - L10 w8: v1(3007,2090) 3007,1998 3020.17,1984.83 v1(3020.17,1840)
NetR169_1: R169.1 Rf+.2 U19.6 | length 137.4
  Bottom Layer - L10 w8: R169.1@719.78,1345.84 725.62,1351.69 745.33,1351.69 Rf+.2@758.25,1364.61 758.25,1363.08 781.33,1340 U19.6@838.33,1340
NetR170_2: R170.2 U20.3 | length 73.3
  Top Layer - L1 w15: U20.3@475.4,1763.28 475.39,1750 500.57,1750 v5(508.05,1742.52)
  Bottom Layer - L10 w16: R170.2@508.02,1718.21 v5(508.05,1742.52)
NetR173_2: R173.2 U21.B1 | length 56.7
  Top Layer - L1 w8: R173.2@86.73,1204.67 86.73,1210.99 113.86,1238.11 U21.B1@113.86,1250.11
NetR175_1: R175.1 U21.A1 | length 45.9
  Top Layer - L1 w8: R175.1@58.73,1234.3 82.3,1234.3 U21.A1@98.11,1250.11
NetR176_1: R176.1 R177.2 U22.4 | length 106.8
  Top Layer - L1 w24: U22.4@520.56,1278.6 564.47,1278.6 R176.1@574.32,1288.44 R177.2@623.32,1288.44
NetR178_1: R178.1 Vcmo.2 | length 549.4
  Signals - L8 w8: v6(945.52,1125) 1193.52,877 Vcmo.2@1369.78,877
  Bottom Layer - L10 w19.68: R178.1@923.07,1125 v6(945.52,1125)
NetRf+_1: Rf+.1 U19.7 | length 42.8
  Bottom Layer - L10 w8: Rf+.1@797.62,1364.61 802.54,1359.68 U19.7@838.33,1359.68
NetRf-_1: Rf-.1 U19.4 | length 42.8
  Bottom Layer - L10 w8: Rf-.1@797.62,1295.71 802.54,1300.63 U19.4@838.33,1300.63
NetRf-_2: Rf-.2 Ri-.2 U19.5 | length 137.4
  Bottom Layer - L10 w8: Ri-.2@719.78,1314.47 725.62,1308.63 745.33,1308.63 Rf-.2@758.25,1295.71 758.25,1297.24 781.33,1320.31 U19.5@838.33,1320.31
NetRo+_1: Ro+.1 U19.13 | length 58.6
  Bottom Layer - L10 w8: U19.13@928.89,1320.31 979.26,1320.31 Ro+.1@985.1,1314.47
NetRo-_1: Ro-.1 U19.12 | length 58.6
  Bottom Layer - L10 w8: U19.12@928.89,1340 979.26,1340 Ro-.1@985.1,1345.84
NetRSV_2: RSV.2 U2.66 | length 445.1
  Bottom Layer - L10 w9: RSV.2@1607.28,702 U2.66@1607.28,1147.09
"NetTs ADD1_2": "Ts ADD1.2" U3.9 | length 166.4
  Top Layer - L1 w10: 2179.28,653 2229.28,703 2229.28,749 2220.89,757.39 U3.9@2183.08,757.39
NetU2_3: U2.3 Vcmo.3 | length 348.4
  Bottom Layer - L10 w9: Vcmo.3@1369.78,977 1452,1059.22 1452,1203 1470.89,1221.89 U2.3@1532.47,1221.89
NetU2_68: U2.68 Vbg.2 | length 179.7
  Bottom Layer - L10 w9: Vbg.2@1544.78,977 1567.91,1000.13 U2.68@1567.91,1147.09
NetU12_3: U12.3 U13.16 | length 1584.7
  Top Layer - L1 w8: v1(4333.14,428.91) 4358.14,403.91 U12.3@4438.76,403.91
  Top Layer - L1 w10: v1(3178.97,287) U13.16@3178.97,340.36
  Bottom Layer - L10 w8: v1(3178.97,287) 3308.97,157 4176,157 4218,199 4218,360.71 4247.29,390 4294.23,390 v1(4333.14,428.91)
NetU12_4: U12.4 U13.17 | length 1495
  Top Layer - L1 w8: v1(3242.83,189.03) 3249.83,196.03 U13.17@3249.83,269.5 ; v1(4333.14,264) 4333.14,354.32 4357.14,378.32 U12.4@4438.76,378.32
  Bottom Layer - L10 w8: v1(3242.83,189.03) 3298.86,133 4267,133 4333.14,199.14 v1(4333.14,264)
NetU12_5: U12.5 U13.18 | length 1542.4
  Top Layer - L1 w8: v1(3248.68,149.19) 3269.52,170.03 U13.18@3269.52,269.5 ; v1(4357.14,240) 4357.14,328.73 4381.14,352.73 U12.5@4462.76,352.73
  Bottom Layer - L10 w8: v1(3248.68,149.19) 3288.86,109 4276.94,109 4357.14,189.2 v1(4357.14,240)
NetU12_6: U12.6 U13.19 | length 1541.7
  Top Layer - L1 w8: v1(3254.52,109.34) 3289.2,144.03 U13.19@3289.2,269.5 ; v1(4381.14,216) 4381.14,303.14 4405.14,327.14 U12.6@4438.76,327.14
  Bottom Layer - L10 w8: v1(3254.52,109.34) 3278.86,85 4286.88,85 4381.14,179.26 v1(4381.14,216)
NetU13_27: U13.27 U18.2 | length 74.8
  Top Layer - L1 w8: v1(3426.68,335.96) 3446.68,315.96 U13.27@3446.68,269.5
NetU13_29: U13.29 U18.1 | length 75.6
  Top Layer - L1 w8: v1(3464.07,335.96) 3486.05,313.98 U13.29@3486.05,269.5
PG_C2M_RX: FMC_RX1.D1 PG_RX1.1 | length 692.9
  Signals - L3 w18: PG_RX1.1@5556,2559 5656,2459 5806,2459 5906,2359 5906,2323 5914,2315 6056,2315 v3(6081,2340)
  Bottom Layer - L10 w18: FMC_RX1.D1@6056,2315 v3(6081,2340)
PG_M2C_RX: FMC_RX1.F1 PG_RX1.2 RR6.1 | length 609.2
  Top Layer - L1 w18: PG_RX1.2@5456,2559 5556,2459 5806,2459 5911.12,2353.88 RR6.1@5911.12,2340 v1(5931,2340)
  Bottom Layer - L10 w18: v1(5931,2340) FMC_RX1.F1@5956,2315
SYNC_N: FMC_RX1.G13 R20.2 | length 4335.8
  Top Layer - L1 w8: R20.2@1669,1707.98 1660,1716.98 1660,1737 1685.5,1762.5 1983.55,1762.5 v1(1994.55,1751.5)
  Signals - L6 w4: v1(1994.55,1751.5) 2004.05,1761 5881,1761 5889,1753 5889,1748 v3(5881,1740)
  Bottom Layer - L10 w8: v3(5881,1740) FMC_RX1.G13@5906,1715
SYNC_P: FMC_RX1.G12 R19.2 | length 4335.9
  Top Layer - L1 w8: R19.2@1642,1707.98 1644,1709.98 1644,1743.63 1678.87,1778.5 v1(1994.55,1778.5)
  Signals - L6 w4: v1(1994.55,1778.5) 2004.05,1769 5860,1769 v3(5881,1790)
  Bottom Layer - L10 w8: v3(5881,1790) FMC_RX1.G12@5906,1765
SYNC_SE: FMC_RX1.H31 R134.1 R143.1 | length 5174
  Signals - L6 w4: v1(2032,1619) 2085,1566 2194,1566 2353,1407 2353,1321 2409,1265 2989,1265 ; 2988.5,1264.5 3010,1243 3010,1153 3023,1140 3055,1140 3068,1153 3068,1176 3157,1265 5561,1265 5711,1115 6043,1115 6056,1102 6056,878 6043,865 5856,865 v3(5831,840)
  Bottom Layer - L10 w8: R143.1@1945.56,1798.5 R134.1@1945.56,1754 1994.36,1705.2 1994.36,1656.64 v1(2032,1619) ; v3(5831,840) FMC_RX1.H31@5856,815
SYNC~/TMST_N: R20.1 R21.1 R23.1 U2.23 | length 178.8
  Top Layer - L1 w8: R20.1@1669.99,1681.01 1672.01,1678.99 R23.1@1697,1678.99
  Bottom Layer - L10 w8: U2.23@1666.33,1532.91 1664.49,1534.76 1664.49,1675.32 v1(1669.99,1680.82)
SYNC~/TMST_P: R18.1 R19.1 R22.1 U2.22 | length 179
  Top Layer - L1 w8: R22.1@1643.01,1653 R19.1@1642.99,1681.01
  Bottom Layer - L10 w8: v1(1642.99,1680.82) 1648.49,1675.31 1648.49,1534.76 U2.22@1646.65,1532.91
SYSREFRX_N: FMC_RX1.G10 R61.2 | length 4198.7
  Signals - L8 w4: v1(1800.99,1837.32) 1787.99,1850.32 1787.99,1858.13 1840.86,1911 5876,1911 5886,1901 5886,1895 v3(5881,1890)
  Bottom Layer - L10 w8: v3(5881,1890) FMC_RX1.G10@5906,1865
SYSREFRX_P: FMC_RX1.G9 R62.2 | length 4198.4
  Signals - L8 w4: v1(1766.99,1837.32) 1779.99,1850.32 1779.99,1861.45 1837.54,1919 5860,1919 v3(5881,1940)
  Bottom Layer - L10 w8: v3(5881,1940) FMC_RX1.G9@5906,1915
SYSREFTX_N: C37.2 R43.2 | length 640.2
  Top Layer - L1 w8: R43.2@1339.1,2106 1321.1,2124 1311.04,2124 1294.23,2107.19 1294.23,1982.37 1479.23,1797.37 1565.25,1797.37 1599.96,1762.66 1599.96,1709.04 C37.2@1604,1705
SYSREFTX_P: C35.2 R44.2 | length 664.5
  Top Layer - L1 w8: R44.2@1339.1,2140 1304.41,2140 1278.23,2113.81 1278.23,1975.74 1315,1938.97 1472.6,1781.37 1558.62,1781.37 1569.93,1770.05 1583.96,1756.03 C35.2@1583.96,1698.02
SYSRF_N: C37.1 C91.1 U2.20 | length 141.9
  Bottom Layer - L10 w8: U2.20@1607.28,1532.91 1605.43,1534.76 1605.43,1666.32 v1(1610.93,1671.82)
SYSRF_P: C35.1 C90.1 U2.19 | length 141.9
  Bottom Layer - L10 w8: C90.1@1583.93,1671.82 1589.43,1666.31 1589.43,1534.76 U2.19@1587.59,1532.91
  other v1: 1583.93,1672.01
TCRIT1: R16.1 R17.1 TCRIT1.1 U3.10 | length 266.6
  Top Layer - L1 w9: U3.10@2183.08,777.07 2253.06,777.07 v1(2265.72,764.41) 2317.13,713 2338.28,713 TCRIT1.1@2398.28,653
TCRIT2: R15.1 TCRIT2.1 U3.11 | length 390.5
  Top Layer - L1 w9: U3.11@2183.08,796.76 2228.28,796.76 v1(2230.28,798.76) 2253.06,798.76 R15.1@2265.72,811.41
  Signals - L6 w9: v1(2230.28,798.76) 2286.49,798.76 2360.25,725 TCRIT2.1@2501.5,725
TCRIT3: R14.1 TCRIT3.1 U3.14 | length 163.8
  Top Layer - L1 w9: U3.14@2183.08,855.81 2265.72,855.81 TCRIT3.1@2265.72,937
TMST_N: R21.2 TMST-.1 | length 1963.2
  Bottom Layer - L10 w8: TMST-.1@100,2330.16 210,2330.16 228.2,2311.95 228.2,2120.03 246.58,2101.66 1068.31,2101.66 1370.6,1799.37 1616.26,1799.37 1663.5,1752.13 1663.5,1713.48 R21.2@1669.99,1706.99
TMST_P: R18.2 TMST+.1 | length 1962.8
  Bottom Layer - L10 w8: TMST+.1@100,1830.16 210,1830.16 228.2,1848.36 228.2,2067.28 246.58,2085.66 1061.68,2085.66 1363.98,1783.37 1609.63,1783.37 1647.5,1745.5 1647.5,1711.5 R18.2@1642.99,1706.99
TRF3765_STROBE: R97.1 R113.1 R116.2 R119.1 U4.5 | length 2323.1
  Top Layer - L1 w8: U4.5@2884.39,1884.49 v1(2884.39,1990) ; R116.2@3913.56,498 R113.1@3913.56,540 R97.1@3960.44,540
  Signals - L3 w4: v1(2884.39,1990) 2884.39,1890 2874.55,1880.16 2874.55,1676.45 2940,1611 2940,1405 3059,1286 3211,1286 3539,958 3681,958 3820,819 v1(3888,819)
  Signals - L6 w4: v1(3888,819) 3888,590.56 v1(3938.56,540)
  Bottom Layer - L10 w8: v1(3938.56,540) R119.1@3960.44,540
TRF_OUTA_N: C112.2 R157.1 R159.2 U17.6 | length 1288.2
  Top Layer - L1 w8: v1(2178.54,1703.5) U17.6@2230.84,1703.5
  Bottom Layer - L10 w8: C112.2@1786.67,2456.69 R157.1@1786.67,2519 1795.67,2528 1795.67,2551.96 1816.71,2573 1893.63,2573 1976.25,2490.38 2042.13,2490.38 2075.5,2457 2075.5,1799.46 2171.46,1703.5 v1(2178.54,1703.5)
TRF_OUTA_P: C113.2 R156.1 R158.2 U17.7 | length 1287.7
  Top Layer - L1 w8: v1(2178.54,1653.5) U17.7@2230.84,1653.5
  Bottom Layer - L10 w8: C113.2@1820.67,2456.69 R156.1@1820.67,2519 1811.67,2528 1811.67,2545.33 1823.34,2557 1887,2557 1969.62,2474.38 2035.5,2474.38 2059.5,2450.38 2059.5,1792.83 2178.54,1673.8 v1(2178.54,1653.5)
TRF_OUTB_N: C33.2 C83.2 R36.2 | length 1614.8
  Top Layer - L1 w8: C33.2@1369.59,1481.45 1359.14,1471 1350.04,1471 1322,1499.04 1322,1595.37 1356.63,1630 1363.95,1630 1373,1620.95 v1(1373,1603.65) ; v1@2360,1792.7 2349,1803.7 2349,1854.5 2398.32,1903.81 2467.42,1903.81 R36.2@2488.05,1883.18 C83.2@2520.36,1883.18
  Signals - L8 w4: v1(1373,1603.65) 1373,1628.65 1380,1635.65 1696.58,1635.65 1720.94,1660 2094.31,1660 2108.81,1674.5 2283.81,1674.5 2341,1731.69 2341,1771 v1(2360,1790)
TRF_OUTB_P: C32.2 C75.2 R29.2 | length 1614.6
  Top Layer - L1 w8: C32.2@1369.59,1454.45 1369.04,1455 1343.41,1455 1306,1492.41 1306,1602 1354.65,1650.65 v1(1373,1650.65) ; v1(2333,1790) 2333,1861.13 2391.69,1919.81 R29.2@2488.05,1919.81 C75.2@2520.36,1919.81
  Signals - L8 w4: v1(1373,1650.65) 1380,1643.65 1693.27,1643.65 1717.62,1668 2091,1668 2105.5,1682.5 2280.5,1682.5 2333,1735 v1(2333,1790)
U2-67: U2.67 | length 14.1
  Bottom Layer - L10 w9: 1587.59,1133 U2.67@1587.59,1147.09
U6-3: U6.3 | length 20.5
  Top Layer - L1 w9: 1577.29,1953.27 U6.3@1577.29,1973.77
U6-4: U6.4 | length 20.5
  Top Layer - L1 w9: 1596.98,1953.27 U6.4@1596.98,1973.77
U6-7: U6.7 | length 20.5
  Top Layer - L1 w9: 1656.03,1953.27 U6.7@1656.03,1973.77
U6-8: U6.8 | length 20.5
  Top Layer - L1 w9: 1675.72,1953.27 U6.8@1675.72,1973.77
U6-9: U6.9 | length 20.5
  Top Layer - L1 w9: 1695.4,1953.27 U6.9@1695.4,1973.77
U6-15: U6.15 | length 20.5
  Top Layer - L1 w9: 1813.51,1953.27 U6.15@1813.51,1973.77
U6-16: U6.16 | length 20.5
  Top Layer - L1 w9: 1833.2,1953.27 U6.16@1833.2,1973.77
